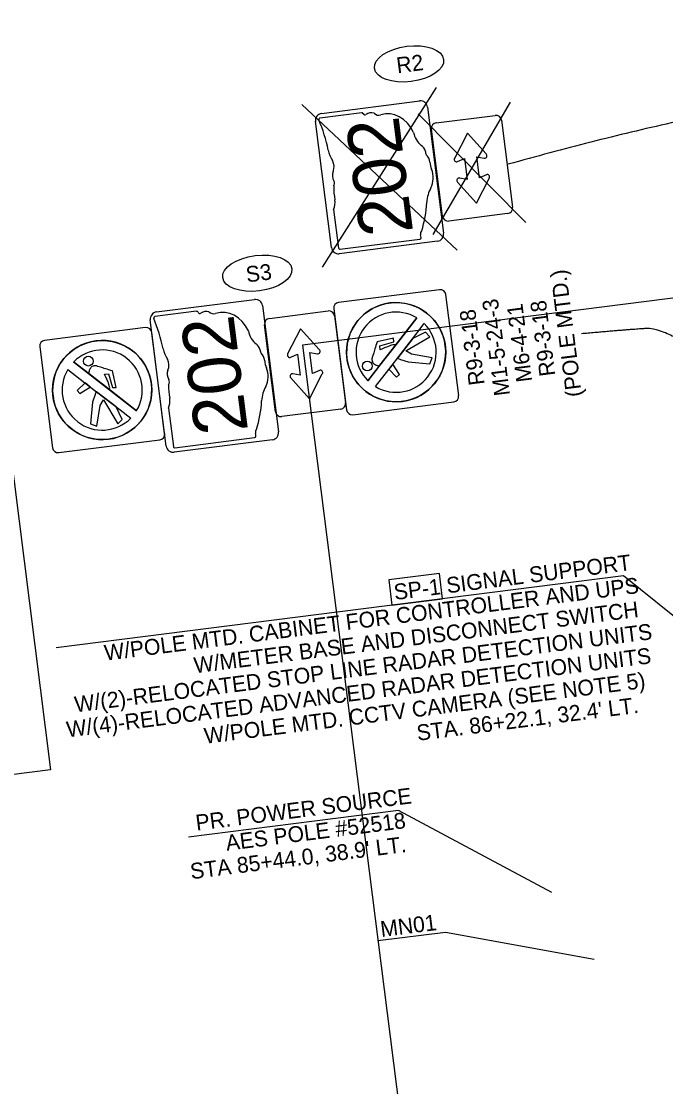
# Model space of a CAD drawing. Extents: x 1509453 to 1510107, y 694919 to 695353.
# Drawn here: x 1509572 to 1509686, y 695121.9 to 695310.3 of the extents above; entities that cross this region are included whole.
import ezdxf

# ---------------------------------------------------------------- set-up
doc = ezdxf.new("R2010")
doc.units = 0
for name, color, linetype in [('LT_P_Luminaires', 7, 'Continuous'), ('LT_P_PullBox', 7, 'Continuous'), ('SC_Scratch5', 7, 'Continuous'), ('SH_Border', 7, 'Continuous'), ('SH_Masking', 7, 'Continuous'), ('SH_Text', 7, 'Continuous')]:
    doc.layers.add(name, color=color, linetype=linetype)

msp = doc.modelspace()

# ---------------------------------------------------------------- linework, layer by layer
at = {"layer": 'LT_P_Luminaires'}
for p, q in [((1509615.93, 695257.72), (1509626.35, 695259.04)), ((1509603.05, 695258.97), (1509595.67, 695258.03)), ((1509603.05, 695258.96), (1509603.05, 695258.97)), ((1509627.47, 695258.17), (1509629.42, 695242.8)), ((1509633.37, 695246.69), (1509642, 695257.82)), ((1509617.02, 695241.22), (1509615.07, 695256.6)), ((1509621.46, 695255.9), (1509619.16, 695251.43)), ((1509624.74, 695252.2), (1509621.46, 695255.9)), ((1509643.54, 695255.28), (1509641.31, 695254.19)), ((1509643.54, 695255.28), (1509641.31, 695254.19)), ((1509644.32, 695254.48), (1509643.54, 695255.28)), ((1509644.32, 695254.48), (1509643.54, 695255.28)), ((1509637.91, 695254.2), (1509634.97, 695253.59)), ((1509637.91, 695254.2), (1509634.97, 695253.59)), ((1509634.97, 695253.59), (1509634.97, 695253.58)), ((1509634.97, 695253.59), (1509634.97, 695253.58)), ((1509635.46, 695252.87), (1509637.93, 695253.56)), ((1509635.46, 695252.87), (1509637.93, 695253.56)), ((1509637.93, 695253.56), (1509637.91, 695254.2)), ((1509637.93, 695253.56), (1509637.91, 695254.2)), ((1509641.31, 695254.19), (1509638.64, 695250.74)), ((1509640.09, 695251.96), (1509644.32, 695254.48)), ((1509640.09, 695251.96), (1509644.32, 695254.48)), ((1509623.57, 695247.98), (1509623.09, 695251.7)), ((1509623.09, 695251.7), (1509624.42, 695251.46)), ((1509635.53, 695252.14), (1509635.46, 695252.87)), ((1509635.53, 695252.14), (1509635.46, 695252.87)), ((1509635.49, 695249.43), (1509638.28, 695253.03)), ((1509641.08, 695251.37), (1509640.09, 695251.96)), ((1509641.08, 695251.37), (1509640.09, 695251.96)), ((1509581.3, 695250.03), (1509592.43, 695241.4)), ((1509619.7, 695250.86), (1509620.92, 695251.42)), ((1509620.92, 695251.42), (1509621.39, 695247.7)), ((1509637.79, 695249.65), (1509637.65, 695249.46)), ((1509638.95, 695247.81), (1509637.79, 695249.65)), ((1509638.95, 695247.81), (1509637.79, 695249.65)), ((1509638.64, 695250.74), (1509638.59, 695250.67)), ((1509638.59, 695250.67), (1509639.13, 695250.47)), ((1509638.59, 695250.67), (1509639.13, 695250.47)), ((1509639.13, 695250.47), (1509640.48, 695250.04)), ((1509639.13, 695250.47), (1509640.48, 695250.04)), ((1509640.48, 695250.04), (1509644.33, 695249.69)), ((1509640.48, 695250.04), (1509644.33, 695249.69)), ((1509644.71, 695250.77), (1509641.08, 695251.37)), ((1509644.71, 695250.77), (1509641.08, 695251.37)), ((1509644.33, 695249.69), (1509644.71, 695250.77)), ((1509644.33, 695249.69), (1509644.71, 695250.77)), ((1509583.92, 695248), (1509584.04, 695247.91)), ((1509584.04, 695247.91), (1509587.64, 695245.12)), ((1509586.75, 695247.88), (1509587.48, 695247.94)), ((1509586.75, 695247.88), (1509587.48, 695247.94)), ((1509587.48, 695247.94), (1509588.17, 695245.47)), ((1509587.48, 695247.94), (1509588.17, 695245.47)), ((1509588.2, 695248.43), (1509588.19, 695248.43)), ((1509588.2, 695248.43), (1509588.19, 695248.43)), ((1509588.81, 695245.5), (1509588.2, 695248.43)), ((1509588.81, 695245.5), (1509588.2, 695248.43)), ((1509621.39, 695247.7), (1509620.07, 695247.93)), ((1509623.03, 695243.5), (1509625.29, 695247.9)), ((1509624.79, 695248.53), (1509623.57, 695247.98)), ((1509635.4, 695249.31), (1509635.49, 695249.43)), ((1509637.08, 695248.72), (1509638.42, 695247.34)), ((1509637.08, 695248.72), (1509638.42, 695247.34)), ((1509638.42, 695247.34), (1509638.95, 695247.81)), ((1509638.42, 695247.34), (1509638.95, 695247.81)), ((1509583.33, 695246.32), (1509581.95, 695244.98)), ((1509583.33, 695246.32), (1509581.95, 695244.98)), ((1509619.69, 695247.25), (1509623.03, 695243.5)), ((1509581.95, 695244.98), (1509582.42, 695244.46)), ((1509581.95, 695244.98), (1509582.42, 695244.46)), ((1509582.42, 695244.46), (1509584.26, 695245.61)), ((1509582.42, 695244.46), (1509584.26, 695245.61)), ((1509584.26, 695245.61), (1509584.07, 695245.75)), ((1509585.08, 695244.27), (1509584.65, 695242.92)), ((1509585.08, 695244.27), (1509584.65, 695242.92)), ((1509585.28, 695244.81), (1509585.08, 695244.27)), ((1509585.28, 695244.81), (1509585.08, 695244.27)), ((1509585.35, 695244.76), (1509585.28, 695244.81)), ((1509588.8, 695242.09), (1509585.35, 695244.76)), ((1509588.17, 695245.47), (1509588.81, 695245.5)), ((1509588.17, 695245.47), (1509588.81, 695245.5)), ((1509584.65, 695242.92), (1509584.3, 695239.07)), ((1509584.65, 695242.92), (1509584.3, 695239.07)), ((1509585.38, 695238.69), (1509585.98, 695242.33)), ((1509585.38, 695238.69), (1509585.98, 695242.33)), ((1509585.98, 695242.33), (1509586.57, 695243.31)), ((1509585.98, 695242.33), (1509586.57, 695243.31)), ((1509586.57, 695243.31), (1509589.09, 695239.08)), ((1509586.57, 695243.31), (1509589.09, 695239.08)), ((1509589.89, 695239.86), (1509588.8, 695242.09)), ((1509589.89, 695239.86), (1509588.8, 695242.09)), ((1509598.07, 695241.86), (1509598.94, 695235.05)), ((1509628.55, 695241.68), (1509618.14, 695240.36)), ((1509584.3, 695239.07), (1509585.38, 695238.69)), ((1509584.3, 695239.07), (1509585.38, 695238.69)), ((1509589.09, 695239.08), (1509589.89, 695239.86)), ((1509589.09, 695239.08), (1509589.89, 695239.86)), ((1509599.21, 695234.85), (1509613.32, 695236.65))]:
    msp.add_line(p, q, dxfattribs=at)
for points in [[(1509646.03, 695262.79), (1509628.18, 695260.53)], [(1509595.94, 695258.85), (1509613.3, 695261.06)], [(1509649.42, 695244.07), (1509647.15, 695261.93)], [(1509614.7, 695259.97), (1509617.53, 695237.65)], [(1509627.31, 695259.41), (1509629.58, 695241.56)], [(1509597.69, 695235.14), (1509594.86, 695257.46)], [(1509642, 695257.82), (1509638.58, 695253.4), (1509638.58, 695253.4), (1509638.58, 695253.4), (1509635.49, 695249.43), (1509635.5, 695249.43)], [(1509594.02, 695256.09), (1509576.17, 695253.83)], [(1509637.65, 695249.46), (1509638.64, 695250.74), (1509641.85, 695254.89), (1509643.32, 695256.79)], [(1509597.4, 695237.37), (1509595.14, 695255.22)], [(1509575.3, 695252.71), (1509577.56, 695234.85)], [(1509584.04, 695247.91), (1509581.3, 695250.03)], [(1509580.27, 695248.7), (1509583.29, 695246.35), (1509584.07, 695245.76), (1509584.07, 695245.75)], [(1509592.43, 695241.4), (1509588.01, 695244.83), (1509588.01, 695244.82), (1509588.01, 695244.83), (1509584.04, 695247.91), (1509584.04, 695247.91)], [(1509584.04, 695247.91), (1509584.04, 695247.91)], [(1509635.49, 695249.43), (1509633.37, 695246.69)], [(1509634.71, 695245.66), (1509637.05, 695248.68), (1509637.64, 695249.46), (1509637.65, 695249.46)], [(1509635.49, 695249.43), (1509635.49, 695249.43)], [(1509637.65, 695249.46), (1509637.08, 695248.72), (1509637.08, 695248.72)], [(1509584.07, 695245.75), (1509583.33, 695246.32), (1509583.33, 695246.32)], [(1509584.07, 695245.75), (1509585.35, 695244.76), (1509589.5, 695241.56), (1509591.41, 695240.08)], [(1509630.69, 695240.69), (1509648.55, 695242.95)], [(1509578.68, 695233.99), (1509596.54, 695236.25)], [(1509616.45, 695236.25), (1509599.09, 695234.05)]]:
    msp.add_lwpolyline(points, dxfattribs=at)
for centre, radius in [((1509638.35, 695251.74), 8.77), ((1509586.35, 695245.05), 8.77), ((1509583.91, 695250.16), 0.864), ((1509633.24, 695249.3), 0.864)]:
    msp.add_circle(centre, radius, dxfattribs=at)
for centre, radius, start, end in [((1509646.16, 695261.8), 1, 7.227, 97.227), ((1509613.46, 695259.82), 1.25, 7.227, 97.227), ((1509626.48, 695258.05), 1, 7.227, 97.227), ((1509628.3, 695259.54), 1, 97.227, 187.227), ((1509638.35, 695251.74), 8.77, 97.227, 277.227), ((1509638.35, 695251.74), 8.77, 277.227, 97.227), ((1509596.1, 695257.61), 1.25, 97.227, 187.227), ((1509616.06, 695256.73), 1, 97.227, 187.227), ((1509638.35, 695251.74), 7.09, 59.046, 225.3983), ((1509638.35, 695251.74), 7.09, 59.046, 225.3983), ((1509594.15, 695255.1), 1, 7.227, 97.227), ((1509638.35, 695251.74), 7.09, 239.0749, 45.4749), ((1509638.35, 695251.74), 7.09, 239.0749, 45.4749), ((1509576.29, 695252.83), 1, 97.227, 187.227), ((1509586.35, 695245.05), 8.77, 7.227, 187.227), ((1509586.35, 695245.05), 7.09, 329.046, 135.3983), ((1509586.35, 695245.05), 7.09, 329.046, 135.3983), ((1509624.49, 695251.87), 0.417, 260.0224, 52.2365), ((1509619.53, 695251.24), 0.417, 152.6382, 294.4316), ((1509586.35, 695245.05), 7.09, 149.0749, 315.4749), ((1509586.35, 695245.05), 7.09, 149.0749, 315.4749), ((1509585.36, 695247.12), 1.54, 149.3021, 149.3553), ((1509620, 695247.52), 0.417, 80.0224, 221.8157), ((1509624.96, 695248.15), 0.417, 322.2174, 114.4316), ((1509636.28, 695250.75), 1.54, 239.3021, 239.3553), ((1509586.35, 695245.05), 8.77, 187.227, 7.227), ((1509648.42, 695243.95), 1, 277.227, 7.227), ((1509628.43, 695242.67), 1, 277.227, 7.227), ((1509618.01, 695241.35), 1, 187.227, 277.227), ((1509630.57, 695241.68), 1, 187.227, 277.227), ((1509596.41, 695237.24), 1, 277.227, 7.227), ((1509616.29, 695237.49), 1.25, 277.227, 7.227), ((1509578.56, 695234.98), 1, 187.227, 277.227), ((1509598.93, 695235.29), 1.25, 187.227, 277.227)]:
    msp.add_arc(centre, radius, start, end, dxfattribs=at)
for centre, major_axis, start_param, end_param in [((1509604.86, 695256.55), (-0.3, 2.4), 5.934695, 6.695948), ((1509607.96, 695252.58), (-0.78, 6.17), 5.101752, 6.440018), ((1509595.67, 695257.77), (-0.033, 0.259), 6.141152, 7.989035), ((1509577.82, 695247.35), (-3.13, 24.66), 4.814394, 5.042369), ((1509603.11, 695258.69), (-0.035, 0.277), 5.05454, 6.418171), ((1509603.6, 695258.98), (-0.051, 0.401), 1.883978, 3.671073), ((1509606.02, 695260.29), (-0.22, 1.75), 2.387724, 3.262537), ((1509614.89, 695256.1), (-0.43, 3.38), 1.647645, 2.488434), ((1509600.98, 695253.48), (-0.63, 4.96), 1.699011, 2.107814), ((1509612.83, 695251.49), (-0.25, 1.99), 4.937069, 5.64225), ((1509614.74, 695251.96), (-0.067, 0.53), 1.147584, 2.315152), ((1509613.59, 695250.08), (-0.24, 1.88), 4.691044, 5.507374), ((1509596.62, 695249.55), (-0.24, 1.89), 4.081561, 5.145723), ((1509617.45, 695250.31), (-0.37, 2.9), 1.495662, 1.94098), ((1509599.12, 695247.81), (-0.2, 1.57), 0.950623, 2.079405), ((1509612.83, 695247.65), (-0.45, 3.54), 4.026481, 4.996735), ((1509605.68, 695245.35), (-1.19, 9.38), 1.404758, 1.657858), ((1509597.63, 695246.5), (-0.096, 0.754), 3.836095, 5.185415), ((1509619.05, 695242.32), (-0.71, 5.57), 0.823519, 1.323587), ((1509596.23, 695243.28), (-0.33, 2.61), 4.042523, 4.731795), ((1509600.16, 695245.31), (-2.26, 17.81), 4.195997, 4.488961), ((1509613.32, 695236.92), (-0.034, 0.272), 3.00124, 4.508301), ((1509614.05, 695237.48), (-0.095, 0.748), 0.519207, 1.627899), ((1509611.87, 695236.78), (-0.26, 2.07), 4.665946, 4.897461), ((1509599.14, 695235.12), (-0.034, 0.269), 1.712693, 3.28349)]:
    msp.add_ellipse(centre, major_axis=major_axis, ratio=0.8, start_param=start_param, end_param=end_param, dxfattribs=at)
for points in [[(1509634.97, 695253.58), (1509634.7, 695252.65), (1509634.24, 695251.19), (1509634.07, 695250.66), (1509634.06, 695250.49), (1509634.08, 695250.32), (1509634.13, 695249.92), (1509634.67, 695249.48), (1509635.12, 695249.38), (1509635.4, 695249.31)], [(1509634.97, 695253.58), (1509634.7, 695252.65), (1509634.24, 695251.19), (1509634.07, 695250.66), (1509634.06, 695250.49), (1509634.08, 695250.32), (1509634.13, 695249.92), (1509634.67, 695249.48), (1509635.12, 695249.38), (1509635.4, 695249.31)], [(1509638.28, 695253.03), (1509638.21, 695253.05), (1509638, 695253.09), (1509637.55, 695253), (1509637.15, 695252.86), (1509636.46, 695252.57), (1509635.98, 695252.36), (1509635.53, 695252.14)], [(1509638.28, 695253.03), (1509638.21, 695253.05), (1509638, 695253.09), (1509637.55, 695253), (1509637.15, 695252.86), (1509636.46, 695252.57), (1509635.98, 695252.36), (1509635.53, 695252.14)], [(1509588.19, 695248.43), (1509587.26, 695248.71), (1509585.8, 695249.16), (1509585.27, 695249.33), (1509585.1, 695249.34), (1509584.93, 695249.32), (1509584.53, 695249.27), (1509584.09, 695248.73), (1509583.99, 695248.28), (1509583.92, 695248)], [(1509588.19, 695248.43), (1509587.26, 695248.71), (1509585.8, 695249.16), (1509585.27, 695249.33), (1509585.1, 695249.34), (1509584.93, 695249.32), (1509584.53, 695249.27), (1509584.09, 695248.73), (1509583.99, 695248.28), (1509583.92, 695248)], [(1509587.64, 695245.12), (1509587.66, 695245.19), (1509587.7, 695245.4), (1509587.61, 695245.85), (1509587.47, 695246.25), (1509587.18, 695246.95), (1509586.97, 695247.43), (1509586.75, 695247.88)], [(1509587.64, 695245.12), (1509587.66, 695245.19), (1509587.7, 695245.4), (1509587.61, 695245.85), (1509587.47, 695246.25), (1509587.18, 695246.95), (1509586.97, 695247.43), (1509586.75, 695247.88)]]:
    msp.add_open_spline(points, degree=3, dxfattribs=at)
at = {"layer": 'LT_P_PullBox'}
for p, q in [((1509625.33, 695266.77), (1509645.49, 695298.56)), ((1509649.14, 695269.79), (1509621.68, 695295.54)), ((1509644.93, 695272.58), (1509658.6, 695295.98)), ((1509632.27, 695294.08), (1509624.88, 695293.14)), ((1509632.26, 695294.07), (1509632.27, 695294.08)), ((1509661.3, 695274.65), (1509642.23, 695293.91)), ((1509645.45, 695292.3), (1509655.87, 695293.62)), ((1509646.54, 695275.81), (1509644.59, 695291.18)), ((1509656.99, 695292.76), (1509658.94, 695277.38)), ((1509650.98, 695290.48), (1509648.68, 695286.02)), ((1509654.26, 695286.79), (1509650.98, 695290.48)), ((1509649.22, 695285.45), (1509650.44, 695286)), ((1509650.44, 695286), (1509650.91, 695282.28)), ((1509653.09, 695282.56), (1509652.61, 695286.28)), ((1509652.61, 695286.28), (1509653.94, 695286.05)), ((1509649.21, 695281.83), (1509652.55, 695278.08)), ((1509650.91, 695282.28), (1509649.59, 695282.52)), ((1509652.55, 695278.08), (1509654.81, 695282.48)), ((1509654.31, 695283.12), (1509653.09, 695282.56)), ((1509627.29, 695276.97), (1509628.15, 695270.16)), ((1509658.07, 695276.26), (1509647.66, 695274.94)), ((1509628.42, 695269.96), (1509642.54, 695271.75))]:
    msp.add_line(p, q, dxfattribs=at)
for points in [[(1509625.15, 695293.96), (1509642.52, 695296.17)], [(1509643.91, 695295.08), (1509646.74, 695272.76)], [(1509626.9, 695270.25), (1509624.07, 695292.57)], [(1509645.66, 695271.36), (1509628.3, 695269.16)]]:
    msp.add_lwpolyline(points, dxfattribs=at)
for centre, radius, start, end in [((1509642.67, 695294.93), 1.25, 7.227, 97.227), ((1509625.31, 695292.72), 1.25, 97.227, 187.227), ((1509656, 695292.63), 1, 7.227, 97.227), ((1509645.58, 695291.31), 1, 97.227, 187.227), ((1509649.05, 695285.83), 0.417, 152.6382, 294.4316), ((1509654.01, 695286.46), 0.417, 260.0224, 52.2365), ((1509649.52, 695282.11), 0.417, 80.0224, 221.8157), ((1509654.48, 695282.74), 0.417, 322.2174, 114.4316), ((1509657.95, 695277.25), 1, 277.227, 7.227), ((1509647.53, 695275.93), 1, 187.227, 277.227), ((1509645.5, 695272.6), 1.25, 277.227, 7.227), ((1509628.14, 695270.4), 1.25, 187.227, 277.227)]:
    msp.add_arc(centre, radius, start, end, dxfattribs=at)
for centre, major_axis, start_param, end_param in [((1509624.88, 695292.88), (-0.033, 0.259), 6.141152, 7.989035), ((1509632.33, 695293.8), (-0.035, 0.277), 5.05454, 6.418171), ((1509632.81, 695294.09), (-0.051, 0.401), 1.883978, 3.671073), ((1509634.07, 695291.66), (-0.3, 2.4), 5.934695, 6.695948), ((1509635.24, 695295.4), (-0.22, 1.75), 2.387724, 3.262537), ((1509637.17, 695287.69), (-0.78, 6.17), 5.101752, 6.440018), ((1509607.03, 695282.46), (-3.13, 24.66), 4.814394, 5.042369), ((1509644.1, 695291.21), (-0.43, 3.38), 1.647645, 2.488434), ((1509630.19, 695288.59), (-0.63, 4.96), 1.699011, 2.107814), ((1509642.05, 695286.6), (-0.25, 1.99), 4.937069, 5.64225), ((1509625.84, 695284.66), (-0.24, 1.89), 4.081561, 5.145723), ((1509643.96, 695287.07), (-0.067, 0.53), 1.147584, 2.315152), ((1509642.81, 695285.19), (-0.24, 1.88), 4.691044, 5.507374), ((1509628.33, 695282.92), (-0.2, 1.57), 0.950623, 2.079405), ((1509646.66, 695285.42), (-0.37, 2.9), 1.495662, 1.94098), ((1509642.04, 695282.76), (-0.45, 3.54), 4.026481, 4.996735), ((1509626.84, 695281.61), (-0.096, 0.754), 3.836095, 5.185415), ((1509634.9, 695280.46), (-1.19, 9.38), 1.404758, 1.657858), ((1509648.26, 695277.43), (-0.71, 5.57), 0.823519, 1.323587), ((1509625.44, 695278.39), (-0.33, 2.61), 4.042523, 4.731795), ((1509629.38, 695280.42), (-2.26, 17.81), 4.195997, 4.488961), ((1509643.26, 695272.59), (-0.095, 0.748), 0.519207, 1.627899), ((1509641.09, 695271.89), (-0.26, 2.07), 4.665946, 4.897461), ((1509642.54, 695272.03), (-0.034, 0.272), 3.00124, 4.508301), ((1509628.36, 695270.23), (-0.034, 0.269), 1.712693, 3.28349)]:
    msp.add_ellipse(centre, major_axis=major_axis, ratio=0.8, start_param=start_param, end_param=end_param, dxfattribs=at)
at = {"layer": 'SH_Border'}
msp.add_lwpolyline([(1509453.15, 695296.65), (1509560.43, 695310.25), (1509577.22, 695177.88), (1509469.93, 695164.28)], close=True, dxfattribs=at)
at = {"layer": 'SH_Masking'}
msp.add_lwpolyline([(1509653.41, 695003.72), (1509839.59, 694987.75), (1509951.38, 695001.93), (1509914.83, 695290.12), (1509834.76, 695254.16), (1509716.56, 695264.98), (1509621.81, 695252.97)], close=True, dxfattribs=at)
at = {"layer": 'SH_Text'}
for p, q in [((1509678.58, 695212.21), (1509578.2, 695199.48)), ((1509744.26, 695159.32), (1509678.58, 695212.21)), ((1509638.79, 695170.71), (1509601.63, 695165.99)), ((1509665.89, 695156.18), (1509638.79, 695170.71)), ((1509647.11, 695149.15), (1509635.12, 695147.63)), ((1509673.37, 695144.37), (1509647.11, 695149.15))]:
    msp.add_line(p, q, dxfattribs=at)
msp.add_lwpolyline([(1509637.62, 695207.01), (1509646.58, 695208.15), (1509646.01, 695212.63), (1509637.05, 695211.5)], close=True, dxfattribs=at)
for centre in [(1509640.63, 695302.72), (1509613.79, 695265.71)]:
    msp.add_ellipse(centre, major_axis=(6.12, 0.78), ratio=0.509473, dxfattribs=at)
for points in [[(1509753.16, 695159.04), (1509768.75, 695161.46), (1509737.84, 695192.48), (1509801.49, 695283.87), (1509773.79, 695304.05), (1509701.06, 695297.04), (1509658.18, 695284.97)], [(1509671.13, 695255.05), (1509679.27, 695255.78), (1509686.04, 695256.19), (1509703.77, 695243.33), (1509708.92, 695229.19), (1509702.79, 695215.9), (1509709.99, 695199.66), (1509723.96, 695198.15), (1509739.06, 695193.88), (1509751.29, 695187.83), (1509753.1, 695173.59), (1509751.47, 695164.87), (1509747.92, 695161.03), (1509744.18, 695159.6)]]:
    msp.add_open_spline(points, degree=2, dxfattribs=at)

# ---------------------------------------------------------------- texts
at = {"layer": 'LT_P_Luminaires'}
msp.add_text('202', height=9.375, rotation=97.227, dxfattribs=at).set_placement((1509612.16, 695237.85))
at = {"layer": 'LT_P_PullBox'}
msp.add_text('202', height=9.375, rotation=97.227, dxfattribs=at).set_placement((1509641.37, 695272.96))
at = {"layer": 'SC_Scratch5'}
for s, p in [('(POLE MTD.)', (1509671.23, 695244)), ('M1-5-24-3', (1509658.5, 695244.19)), ('R9-3-18', (1509654.03, 695246.06)), ('M6-4-21', (1509662.43, 695246.62)), ('R9-3-18', (1509666.53, 695247.65))]:
    msp.add_text(s, height=2.8, rotation=97.227, dxfattribs=at).set_placement(p)
at = {"layer": 'SH_Text'}
for s, p in [('R2', (1509638.58, 695301.05)), ('S3', (1509611.95, 695264.07)), ('SP-1 SIGNAL SUPPORT', (1509638.13, 695207.91)), ('W/POLE MTD. CABINET FOR CONTROLLER AND UPS', (1509586.9, 695197.18)), ('W/METER BASE AND DISCONNECT SWITCH', (1509602.75, 695194.96)), ('W/(2)-RELOCATED STOP LINE RADAR DETECTION UNITS', (1509581.63, 695188.05)), ('W/(4)-RELOCATED ADVANCED RADAR DETECTION UNITS', (1509580.21, 695183.63)), ('W/POLE MTD. CCTV CAMERA (SEE NOTE 5)', (1509604.57, 695182.49)), ("STA. 86+22.1, 32.4' LT.", (1509642.17, 695183.02)), ('PR. POWER SOURCE', (1509603.06, 695167.13)), ('AES POLE #52518', (1509608.38, 695163.57)), ("STA 85+44.0, 38.9' LT.", (1509602.1, 695158.54)), ('MN01', (1509635.74, 695148.31))]:
    msp.add_text(s, height=2.8, rotation=7.227, dxfattribs=at).set_placement(p)

doc.saveas('drawing.dxf')
